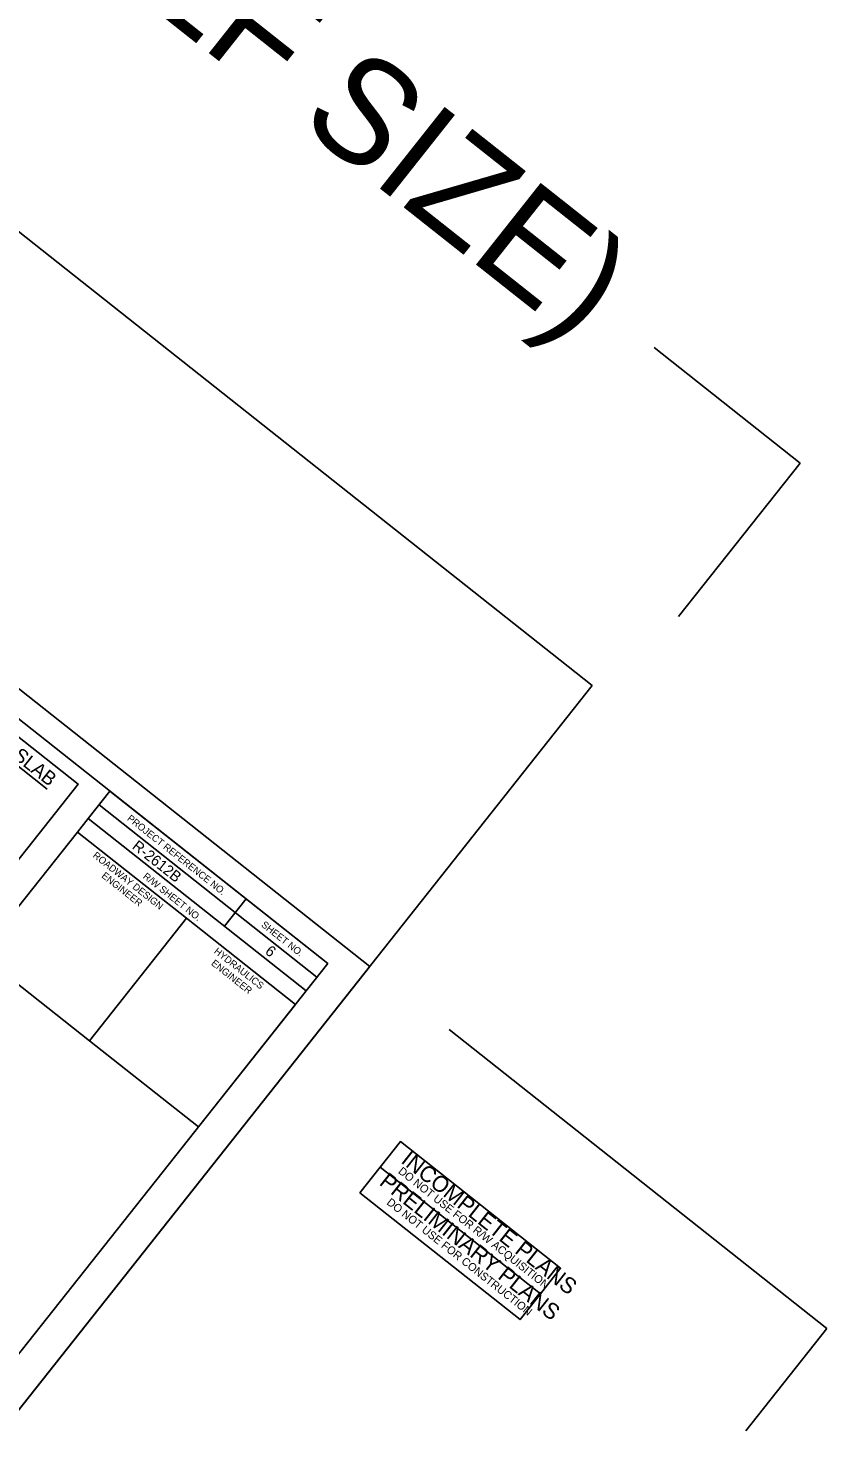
# Model space of a CAD drawing. Extents: x 1771636 to 1784627, y 798645 to 819978.
# Drawn here: x 1784052 to 1784627, y 812169 to 813181 of the extents above; entities that cross this region are included whole.
import ezdxf

# ---------------------------------------------------------------- set-up
doc = ezdxf.new("R2010")
doc.units = 0
for name, color, linetype in [('Exist Hydro Stream Flow Arrow CELL', 7, 'Continuous'), ('Exist Other Culture Area Outline', 7, 'Continuous'), ('Exist Other Culture Well CELL', 7, 'Continuous'), ('Exist Roads EOP', 7, 'Continuous'), ('Exist Utilities Power Joint Use Telephone CELL', 7, 'Continuous'), ('Exist Utilities Power Pole CELL', 7, 'Continuous'), ('Exist Utilities Water Fire Hydrant CELL', 7, 'Continuous'), ('Exist Vegetation Woods Line', 7, 'Continuous')]:
    doc.layers.add(name, color=color, linetype=linetype)

msp = doc.modelspace()

# ---------------------------------------------------------------- linework, layer by layer
at = {"layer": 'Exist Hydro Stream Flow Arrow CELL'}
msp.add_lwpolyline([(1784297.9, 812505.9), (1781710.6, 814554.3), (1780665.3, 813234), (1783252.6, 811185.6)], close=True, dxfattribs=at)
at = {"layer": 'Exist Other Culture Area Outline'}
msp.add_lwpolyline([(1784290.8, 812343.1), (1784305.4, 812361.6), (1784420.7, 812270.3), (1784406.1, 812251.9)], close=True, dxfattribs=at)
at = {"layer": 'Exist Other Culture Well CELL'}
msp.add_lwpolyline([(1784458, 812708.2), (1781817.4, 814798.8), (1780451.8, 813073.9), (1783092.4, 810983.3)], close=True, dxfattribs=at)
at = {"layer": 'Exist Roads EOP'}
msp.add_lwpolyline([(1784305.4, 812361.6), (1784320, 812380), (1784435.2, 812288.8), (1784420.7, 812270.3)], close=True, dxfattribs=at)
at = {"layer": 'Exist Utilities Power Joint Use Telephone CELL'}
for p, q in [((1784607.6, 812868.3), (1784502.6, 812951.5)), ((1784520.1, 812757.8), (1784607.6, 812868.3)), ((1784103.1, 812622.4), (1784259.9, 812498.3)), ((1784095.3, 812612.6), (1784087.6, 812602.8)), ((1784095.3, 812612.6), (1784252.2, 812488.5)), ((1784208.9, 812554.6), (1784193.4, 812535)), ((1784355, 812460.7), (1784626.8, 812245.5)), ((1784626.8, 812245.5), (1784568.4, 812171.7))]:
    msp.add_line(p, q, dxfattribs=at)
for points in [[(1781915.6, 814370.3), (1784267.7, 812508.1), (1783243.5, 811214.5), (1780891.4, 813076.6)], [(1784110.9, 812632.3), (1784267.7, 812508.1), (1784252.2, 812488.5), (1784095.3, 812612.6)], [(1784087.6, 812602.8), (1784166, 812540.7), (1784096.2, 812452.5), (1784017.7, 812514.6)], [(1784166, 812540.7), (1784244.4, 812478.7), (1784174.6, 812390.5), (1784096.2, 812452.5)]]:
    msp.add_lwpolyline(points, close=True, dxfattribs=at)
at = {"layer": 'Exist Utilities Water Fire Hydrant CELL'}
msp.add_line((1783946.2, 812728.4), (1784065.9, 812633.7), dxfattribs=at)
at = {"layer": 'Exist Vegetation Woods Line'}
msp.add_lwpolyline([(1783405.8, 813177.4), (1784088, 812637.3), (1783973.7, 812492.9), (1783291.5, 813033)], close=True, dxfattribs=at)

# ---------------------------------------------------------------- texts
at = {"layer": 'Exist Other Culture Area Outline'}
for s, height, p in [('PRELIMINARY PLANS', 11.52, (1784304.1, 812349.4)), ('DO NOT USE FOR CONSTRUCTION', 5.76, (1784309.6, 812335.3))]:
    msp.add_text(s, height=height, rotation=321.6309, dxfattribs=at).set_placement(p)
at = {"layer": 'Exist Roads EOP'}
for s, height, p in [('INCOMPLETE PLANS', 11.52, (1784319.7, 812365.2)), ('DO NOT USE FOR R/W ACQUISITION', 5.76, (1784317.9, 812357.7))]:
    msp.add_text(s, height=height, rotation=321.6309, dxfattribs=at).set_placement(p)
at = {"layer": 'Exist Utilities Power Joint Use Telephone CELL'}
for s, height, p in [('TO PLOT 34"(HALF SIZE)', 75, (1783522.9, 813685.3)), ('PROJECT REFERENCE NO.', 5, (1784122.9, 812611.7)), ('ROADWAY DESIGN', 5, (1784098.2, 812585.1)), ('ENGINEER', 5, (1784104.5, 812570.5)), ('R/W SHEET NO.', 5, (1784134.3, 812570)), ('SHEET NO.', 5, (1784219.4, 812535.2)), ('HYDRAULICS', 5, (1784185.4, 812516.1)), ('ENGINEER', 5, (1784183.4, 812507.5))]:
    msp.add_text(s, height=height, rotation=321.6309, dxfattribs=at).set_placement(p)
at = {"layer": 'Exist Utilities Power Pole CELL'}
for s, p in [('R-2612B  ', (1784126.4, 812591.4)), ('6', (1784222, 812515.8))]:
    msp.add_text(s, height=7.75, rotation=321.6309, dxfattribs=at).set_placement(p)
at = {"layer": 'Exist Utilities Water Fire Hydrant CELL'}
msp.add_text('END APPROACH SLAB', height=10, rotation=321.6596, dxfattribs=at).set_placement((1783953.8, 812725.1))

doc.saveas('drawing.dxf')
